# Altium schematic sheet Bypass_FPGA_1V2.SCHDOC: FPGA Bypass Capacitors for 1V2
size A4; Organization: Altium Limited.; Address1: Level 3, 12a Rodborough Rd; Address2: Frenchs Forest 2086; Address3: NSW; Address4: AUSTRALIA; SheetNumber: 5; SheetTotal: 21
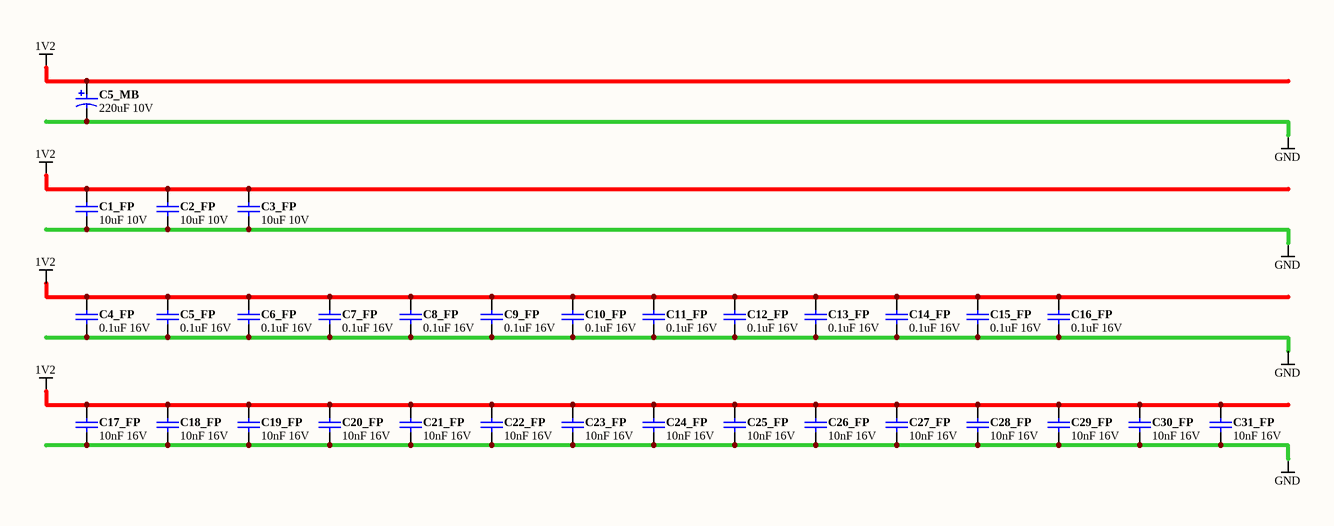
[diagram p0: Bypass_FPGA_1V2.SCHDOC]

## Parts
C1_FP  10uF 10V  [CAPC2012-STAR]
C2_FP  10uF 10V  [CAPC2012-STAR]
C3_FP  10uF 10V  [CAPC2012-STAR]
C4_FP  0.1uF 16V  [CAPC1005-STAR]
C5_FP  0.1uF 16V  [CAPC1005-STAR]
C5_MB  220uF 10V  [CAPC7343-STAR]
C6_FP  0.1uF 16V  [CAPC1005-STAR]
C7_FP  0.1uF 16V  [CAPC1005-STAR]
C8_FP  0.1uF 16V  [CAPC1005-STAR]
C9_FP  0.1uF 16V  [CAPC1005-STAR]
C10_FP  0.1uF 16V  [CAPC1005-STAR]
C11_FP  0.1uF 16V  [CAPC1005-STAR]
C12_FP  0.1uF 16V  [CAPC1005-STAR]
C13_FP  0.1uF 16V  [CAPC1005-STAR]
C14_FP  0.1uF 16V  [CAPC1005-STAR]
C15_FP  0.1uF 16V  [CAPC1005-STAR]
C16_FP  0.1uF 16V  [CAPC1005-STAR]
C17_FP  10nF 16V  [CAPC1005-STAR]
C18_FP  10nF 16V  [CAPC1005-STAR]
C19_FP  10nF 16V  [CAPC1005-STAR]
C20_FP  10nF 16V  [CAPC1005-STAR]
C21_FP  10nF 16V  [CAPC1005-STAR]
C22_FP  10nF 16V  [CAPC1005-STAR]
C23_FP  10nF 16V  [CAPC1005-STAR]
C24_FP  10nF 16V  [CAPC1005-STAR]
C25_FP  10nF 16V  [CAPC1005-STAR]
C26_FP  10nF 16V  [CAPC1005-STAR]
C27_FP  10nF 16V  [CAPC1005-STAR]
C28_FP  10nF 16V  [CAPC1005-STAR]
C29_FP  10nF 16V  [CAPC1005-STAR]
C30_FP  10nF 16V  [CAPC1005-STAR]
C31_FP  10nF 16V  [CAPC1005-STAR]

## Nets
1V2: C1_FP.1 C2_FP.1 C3_FP.1 C4_FP.1 C5_FP.1 C5_MB.1 C6_FP.1 C7_FP.1 C8_FP.1 C9_FP.1 C10_FP.1 C11_FP.1 C12_FP.1 C13_FP.1 C14_FP.1 C15_FP.1 C16_FP.1 C17_FP.1 C18_FP.1 C19_FP.1 C20_FP.1 C21_FP.1 C22_FP.1 C23_FP.1 C24_FP.1 C25_FP.1 C26_FP.1 C27_FP.1 C28_FP.1 C29_FP.1 C30_FP.1 C31_FP.1
GND: C1_FP.2 C2_FP.2 C3_FP.2 C4_FP.2 C5_FP.2 C5_MB.2 C6_FP.2 C7_FP.2 C8_FP.2 C9_FP.2 C10_FP.2 C11_FP.2 C12_FP.2 C13_FP.2 C14_FP.2 C15_FP.2 C16_FP.2 C17_FP.2 C18_FP.2 C19_FP.2 C20_FP.2 C21_FP.2 C22_FP.2 C23_FP.2 C24_FP.2 C25_FP.2 C26_FP.2 C27_FP.2 C28_FP.2 C29_FP.2 C30_FP.2 C31_FP.2

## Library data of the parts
C1_FP C2_FP C3_FP = D-101-0087: Capacitor, Ceramic, 10uF 10% 10V 0805 (2012) X5R; Polarity: Non-Polarized
C4_FP C5_FP C6_FP C7_FP C8_FP C9_FP C10_FP C11_FP C12_FP C13_FP C14_FP C15_FP C16_FP = D-101-0080: Capacitor, Ceramic, 0.1uF 10% 16V 0402 (1005) X7R; Polarity: Non-Polarized
C5_MB = D-101-0088: Capacitor, Tantalum, 220uF 10% 10V MCCT-D (7343-31); Polarity: Polarized
C17_FP C18_FP C19_FP C20_FP C21_FP C22_FP C23_FP C24_FP C25_FP C26_FP C27_FP C28_FP C29_FP C30_FP C31_FP = D-101-0077: Capacitor, Ceramic, 10nF 10% 16V 0402 (1005) X7R; Polarity: Non-Polarized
